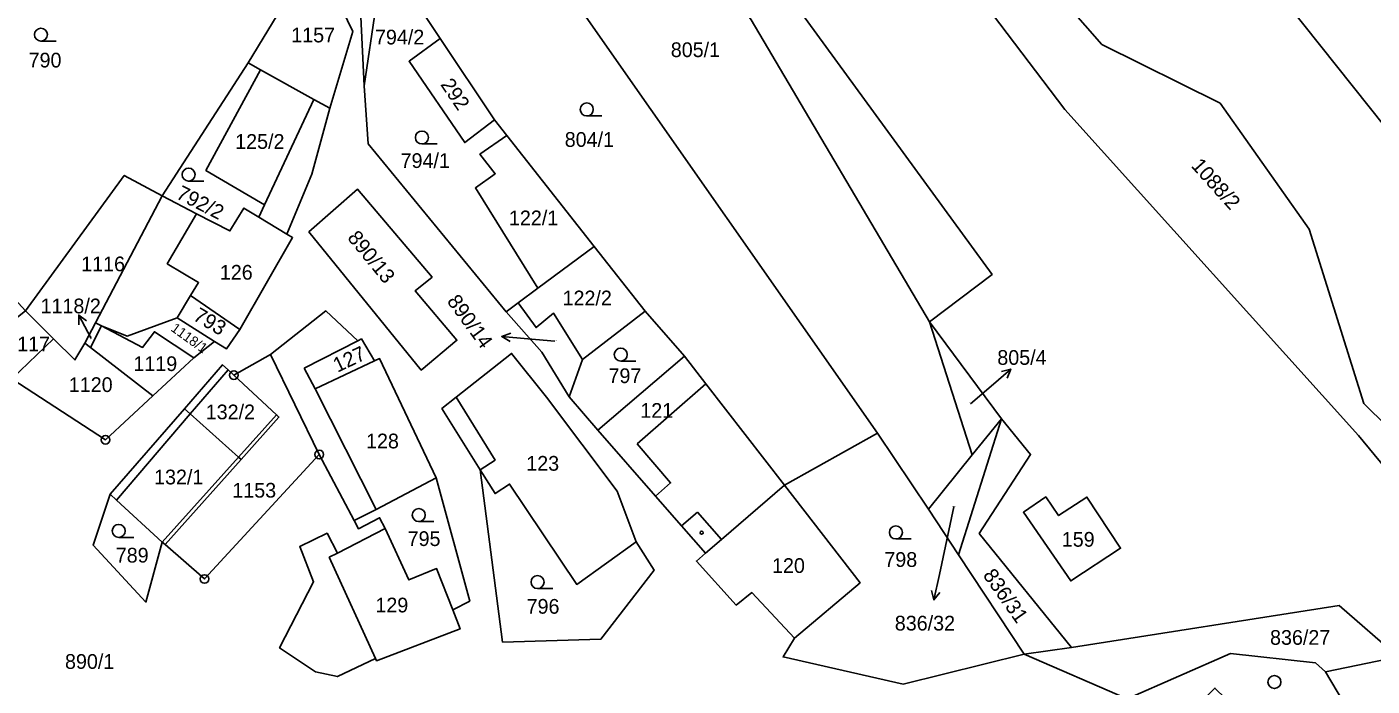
# Model space of a CAD drawing. Extents: x -654083 to -650132, y -1099819 to -1096699.
# Drawn here: x -653060.7 to -652905.4, y -1098197.5 to -1098121.3 of the extents above; entities that cross this region are included whole.
import ezdxf

# ---------------------------------------------------------------- set-up
doc = ezdxf.new("R2010")
doc.units = 0
for name, color, linetype in [('Geodetické body', 7, 'Continuous'), ('Hranice - vnitř_ kresba', 7, 'Continuous'), ('Obvody jako plochy', 7, 'Continuous'), ('Parcelní čísla', 7, 'Continuous'), ('Prvky pro prodl_ par_ č_', 7, 'Continuous'), ('Značky kultur', 7, 'Continuous'), ('Značky na budově ne v SPI', 7, 'Continuous')]:
    doc.layers.add(name, color=color, linetype=linetype)

msp = doc.modelspace()

# ---------------------------------------------------------------- linework, layer by layer
at = {"layer": 'Geodetické body'}
for centre, radius in [((-653036.79, -1098161.57), 0.5), ((-653036.79, -1098161.57), 0.001), ((-653051.6, -1098169.04), 0.5), ((-653051.6, -1098169.04), 0.001), ((-653026.93, -1098170.74), 0.5), ((-653026.93, -1098170.74), 0.001), ((-653040.19, -1098185.12), 0.5), ((-653040.19, -1098185.12), 0.001)]:
    msp.add_circle(centre, radius, dxfattribs=at)
at = {"layer": 'Hranice - vnitř_ kresba'}
for p, q in [((-653027.56, -1098129.72), (-653033.25, -1098141.9)), ((-653041.09, -1098142.92), (-653044.47, -1098148.7)), ((-653044.47, -1098148.7), (-653040.87, -1098150.87)), ((-653040.87, -1098150.87), (-653041.78, -1098152.37)), ((-653022.48, -1098157.6), (-653028.69, -1098160.78)), ((-653041.82, -1098166.06), (-653037.45, -1098160.96)), ((-653028.69, -1098160.78), (-653027.4, -1098163.17)), ((-652982.31, -1098162.56), (-652990.26, -1098169.5)), ((-653006.65, -1098171.38), (-653011.14, -1098164.13)), ((-653050.34, -1098176), (-653041.82, -1098166.06)), ((-653031.87, -1098166.14), (-653036.26, -1098171.03)), ((-652990.26, -1098169.5), (-652986.4, -1098174.03)), ((-653036.26, -1098171.03), (-653045.08, -1098180.85)), ((-653008.37, -1098172.52), (-653006.65, -1098171.38)), ((-652986.4, -1098174.03), (-652988.14, -1098175.54)), ((-652985.12, -1098178.98), (-652983.28, -1098177.39)), ((-652983.28, -1098177.39), (-652980.52, -1098180.55)), ((-653025.78, -1098182.59), (-653024.83, -1098182.13)), ((-653020.45, -1098194.29), (-653025.78, -1098182.59))]:
    msp.add_line(p, q, dxfattribs=at)
at = {"layer": 'Obvody jako plochy'}
for points in [[(-652950.77, -1098179.85), (-652944.85, -1098170.74), (-652948.2, -1098166.63), (-652956.52, -1098155.41), (-652949.3, -1098149.94), (-653000.03, -1098080.28), (-653002.88, -1098076.39), (-653023.81, -1098046.42), (-653037.15, -1098027.99), (-653053.39, -1098005.53), (-653071.26, -1097984.33), (-653150.23, -1097911.49), (-653215.43, -1097850.17), (-653263.01, -1097791.35), (-653289.74, -1097748.95), (-653316.6, -1097720.46)], [(-653147.91, -1097892.43), (-653087.66, -1097949.15), (-653051.69, -1097985.74), (-653044.45, -1097994.63), (-653022.76, -1098022.08), (-653010.09, -1098039.2), (-653001.74, -1098050.56), (-652940.91, -1098130.87), (-652906.99, -1098168.54), (-652893.23, -1098185.24), (-652886.09, -1098193.05), (-652844.83, -1098239.19), (-652818.94, -1098266.58), (-652768.04, -1098305.36), (-652748.77, -1098307.6), (-652729.64, -1098315.8), (-652661.4, -1098344.97)], [(-653062.42, -1098161.99), (-653051.6, -1098169.04), (-653046.15, -1098163.95), (-653041.4, -1098159.57), (-653039.02, -1098157.69), (-653037.66, -1098158.54), (-653036.1, -1098156.28), (-653030.01, -1098145.69), (-653030.68, -1098145.29), (-653027.79, -1098138.35), (-653025.7, -1098130.74), (-653023.08, -1098121.88), (-653027.32, -1098113)], [(-653022.15, -1098120.19), (-653021.74, -1098128.17), (-653021.28, -1098134.84), (-653005.37, -1098154.24), (-653001.25, -1098158.93), (-652998.11, -1098164.06), (-652994.8, -1098167.94), (-652988.14, -1098175.54), (-652985.12, -1098178.98), (-652982.36, -1098182.14), (-652983.42, -1098183.05), (-652978.83, -1098188.14), (-652977.01, -1098186.69), (-652972.08, -1098191.95), (-652973.42, -1098194.12), (-652959.54, -1098197.26), (-652945.6, -1098193.8), (-652933.7, -1098198.95)], [(-652631.34, -1098381.55), (-652704.64, -1098360.24), (-652738.94, -1098344.05), (-652737.17, -1098341.14), (-652773.8, -1098320.71), (-652795.83, -1098304.08), (-652826.4, -1098281.98), (-652836.28, -1098271.18), (-652854.98, -1098250.17), (-652884.09, -1098215.25), (-652902.43, -1098194.12), (-652909.24, -1098188.18), (-652940.14, -1098193.04), (-652950.77, -1098179.85)]]:
    msp.add_lwpolyline(points, dxfattribs=at)
for points in [[(-652964.91, -1098091.06), (-652936.61, -1098123.36), (-652922.98, -1098130.17), (-652912.71, -1098144.71), (-652906.4, -1098164.85), (-652887.47, -1098183.54), (-652893.23, -1098185.24), (-652906.99, -1098168.54), (-652940.91, -1098130.87), (-653001.74, -1098050.56), (-653006.39, -1098039.49), (-653002.23, -1098043.75), (-653002.01, -1098044.84), (-653000.6, -1098046.56), (-652987.25, -1098065.01), (-652985.49, -1098067.13), (-652981.58, -1098071.85), (-652973.42, -1098084.42), (-652967.92, -1098092.9)], [(-652825.33, -1098183.34), (-652882.35, -1098128.31), (-652938.91, -1098065.46), (-652934.7, -1098072.57), (-652944.94, -1098078.84), (-652930.2, -1098099.86), (-652898.24, -1098140.05), (-652895.53, -1098138.3), (-652860.37, -1098179.33), (-652847.2, -1098177.03)], [(-652860.37, -1098179.33), (-652847.2, -1098177.03), (-652825.33, -1098183.34), (-652810.18, -1098187.08), (-652821.22, -1098189.78), (-652834.98, -1098189.5), (-652863.77, -1098185.22), (-652887.47, -1098183.54), (-652906.4, -1098164.85), (-652912.71, -1098144.71), (-652922.98, -1098130.17), (-652936.61, -1098123.36), (-652964.91, -1098091.06), (-652955.6, -1098085.37), (-652944.94, -1098078.84), (-652930.2, -1098099.86), (-652898.24, -1098140.05), (-652895.53, -1098138.3)], [(-653000.03, -1098080.28), (-652949.3, -1098149.94), (-652956.52, -1098155.41), (-652977.11, -1098120.51), (-652997.92, -1098090.84), (-653000.67, -1098088.48), (-653003.49, -1098086.07)], [(-652956.65, -1098177.05), (-652962.52, -1098168.29), (-652997.48, -1098118.28), (-653011.5, -1098101.65), (-653002.18, -1098090.99), (-652997.92, -1098090.84), (-652977.11, -1098120.51), (-652956.52, -1098155.41), (-652951.59, -1098170.76)], [(-653053.71, -1098110.99), (-653055.61, -1098113.11), (-653074.21, -1098095.28), (-653077.11, -1098098), (-653091.4, -1098111.38), (-653093.32, -1098113.17), (-653082.85, -1098128.85), (-653078.13, -1098135.23), (-653060.83, -1098154.16), (-653049.44, -1098138.5), (-653045.05, -1098140.86), (-653035.15, -1098125.51), (-653030.07, -1098117.11), (-653027.32, -1098113), (-653031.29, -1098104.31), (-653037.53, -1098097.49), (-653052.73, -1098111.83)], [(-652984.78, -1098159.38), (-652989.31, -1098154.19), (-652995.2, -1098146.7), (-653005.28, -1098133.9), (-653006.71, -1098132.09), (-653012.97, -1098122.69), (-653019.03, -1098113.59), (-653011.5, -1098101.65), (-652997.48, -1098118.28), (-652962.52, -1098168.29), (-652973.23, -1098174.28), (-652982.31, -1098162.56)], [(-653027.56, -1098129.72), (-653025.7, -1098130.74), (-653023.08, -1098121.88), (-653027.32, -1098113), (-653030.07, -1098117.11), (-653035.15, -1098125.51), (-653033.73, -1098126.3)], [(-653019.82, -1098112.88), (-653019.03, -1098113.59), (-653020.41, -1098119.07), (-653021.74, -1098128.17), (-653022.15, -1098120.19)], [(-653008.39, -1098136.05), (-653006.63, -1098138.31), (-653008.92, -1098139.94), (-653001.7, -1098151.52), (-653003.97, -1098153.21), (-653005.37, -1098154.24), (-653021.28, -1098134.84), (-653021.74, -1098128.17), (-653020.41, -1098119.07), (-653019.03, -1098113.59), (-653012.97, -1098122.69), (-653016.58, -1098125.32), (-653010.15, -1098134.7), (-653006.71, -1098132.09), (-653005.28, -1098133.9)], [(-653006.71, -1098132.09), (-653012.97, -1098122.69), (-653016.58, -1098125.32), (-653010.15, -1098134.7)], [(-653012.97, -1098122.69), (-653016.58, -1098125.32), (-653010.15, -1098134.7), (-653006.71, -1098132.09)], [(-653033.25, -1098141.9), (-653040.01, -1098137.93), (-653033.73, -1098126.3), (-653035.15, -1098125.51), (-653045.05, -1098140.86), (-653041.09, -1098142.92), (-653037.25, -1098144.91), (-653035.64, -1098142.27), (-653033.92, -1098143.34)], [(-653027.56, -1098129.72), (-653033.73, -1098126.3), (-653040.01, -1098137.93), (-653033.25, -1098141.9), (-653033.92, -1098143.34), (-653030.68, -1098145.29), (-653027.79, -1098138.35), (-653025.7, -1098130.74)], [(-653027.56, -1098129.72), (-653033.25, -1098141.9), (-653040.01, -1098137.93), (-653033.73, -1098126.3)], [(-653001.7, -1098151.52), (-652995.2, -1098146.7), (-653005.28, -1098133.9), (-653008.39, -1098136.05), (-653006.63, -1098138.31), (-653008.92, -1098139.94)], [(-653005.28, -1098133.9), (-653008.39, -1098136.05), (-653006.63, -1098138.31), (-653008.92, -1098139.94), (-653001.7, -1098151.52), (-652995.2, -1098146.7)], [(-653053.99, -1098157.86), (-653052.76, -1098155.51), (-653045.05, -1098140.86), (-653049.44, -1098138.5), (-653060.83, -1098154.16), (-653057.61, -1098157.36), (-653055.14, -1098159.81)], [(-653015.86, -1098151.82), (-653013.92, -1098150.25), (-653022.51, -1098140.09), (-653028.14, -1098145.02), (-653015.17, -1098160.98), (-653011.05, -1098157.55)], [(-653011.05, -1098157.55), (-653015.86, -1098151.82), (-653013.92, -1098150.25), (-653022.51, -1098140.09), (-653028.14, -1098145.02), (-653015.17, -1098160.98)], [(-653033.92, -1098143.34), (-653030.68, -1098145.29), (-653030.01, -1098145.69), (-653036.1, -1098156.28), (-653041.78, -1098152.37), (-653043.35, -1098154.95), (-653049.1, -1098157.08), (-653052.08, -1098155.86), (-653052.76, -1098155.51), (-653045.05, -1098140.86), (-653041.09, -1098142.92), (-653037.25, -1098144.91), (-653035.64, -1098142.27)], [(-653041.09, -1098142.92), (-653044.47, -1098148.7), (-653040.87, -1098150.87), (-653041.78, -1098152.37), (-653036.1, -1098156.28), (-653030.01, -1098145.69), (-653030.68, -1098145.29), (-653033.92, -1098143.34), (-653035.64, -1098142.27), (-653037.25, -1098144.91)], [(-652995.2, -1098146.7), (-652989.31, -1098154.19), (-652996.57, -1098159.75), (-652999.89, -1098154.43), (-653001.92, -1098156.08), (-653003.97, -1098153.21), (-653001.7, -1098151.52)], [(-653003.97, -1098153.21), (-653001.7, -1098151.52), (-652995.2, -1098146.7), (-652989.31, -1098154.19), (-652996.57, -1098159.75), (-652999.89, -1098154.43), (-653001.92, -1098156.08)], [(-653041.78, -1098152.37), (-653043.35, -1098154.95), (-653039.02, -1098157.69), (-653037.66, -1098158.54), (-653036.1, -1098156.28)], [(-652996.57, -1098159.75), (-652998.11, -1098164.06), (-653001.25, -1098158.93), (-653005.37, -1098154.24), (-653003.97, -1098153.21), (-653001.92, -1098156.08), (-652999.89, -1098154.43)], [(-653062.42, -1098161.99), (-653066.55, -1098158.69), (-653060.83, -1098154.16), (-653057.61, -1098157.36)], [(-653053.32, -1098158.38), (-653052.08, -1098155.86), (-653052.76, -1098155.51), (-653053.99, -1098157.86)], [(-653045.08, -1098180.85), (-653044.73, -1098181.12), (-653040.19, -1098185.12), (-653026.93, -1098170.74), (-653022.92, -1098178.35), (-653022.41, -1098179.32), (-653019.98, -1098178.04), (-653019.32, -1098179.29), (-653024.83, -1098182.13), (-653026.03, -1098179.83), (-653029.18, -1098181.38), (-653027.6, -1098185.43), (-653031.51, -1098193.08), (-653027.37, -1098195.85), (-653024.85, -1098196.4), (-653020.45, -1098194.29), (-653020.32, -1098194.57), (-653010.68, -1098190.88), (-653011.54, -1098188.67), (-653009.58, -1098187.67), (-653013.46, -1098173.45), (-653019.98, -1098159.66), (-653020.56, -1098159.93), (-653022.08, -1098157.39), (-653022.48, -1098157.6), (-653026.19, -1098154.16), (-653032.56, -1098159.17), (-653036.79, -1098161.57), (-653037.45, -1098160.96), (-653038.09, -1098160.38), (-653042.5, -1098165.46), (-653051.07, -1098175.33), (-653053.03, -1098181.23), (-653046.94, -1098187.78)], [(-653043.35, -1098154.95), (-653039.02, -1098157.69), (-653041.4, -1098159.57), (-653045.96, -1098156.56), (-653047.32, -1098158.36), (-653052.08, -1098155.86), (-653049.1, -1098157.08)], [(-653020.36, -1098177.08), (-653022.92, -1098178.35), (-653026.93, -1098170.74), (-653032.56, -1098159.17), (-653026.19, -1098154.16), (-653022.48, -1098157.6), (-653022.08, -1098157.39), (-653020.56, -1098159.93), (-653027.4, -1098163.17)], [(-652984.78, -1098159.38), (-652994.8, -1098167.94), (-652998.11, -1098164.06), (-652996.57, -1098159.75), (-652989.31, -1098154.19)], [(-652956.52, -1098155.41), (-652948.2, -1098166.63), (-652951.59, -1098170.76)], [(-653041.4, -1098159.57), (-653045.96, -1098156.56), (-653047.32, -1098158.36), (-653052.08, -1098155.86), (-653053.32, -1098158.38), (-653046.15, -1098163.95)], [(-653055.14, -1098159.81), (-653057.61, -1098157.36), (-653062.42, -1098161.99), (-653051.6, -1098169.04), (-653046.15, -1098163.95), (-653053.32, -1098158.38), (-653053.99, -1098157.86)], [(-653028.69, -1098160.78), (-653027.4, -1098163.17), (-653020.56, -1098159.93), (-653022.08, -1098157.39), (-653022.48, -1098157.6)], [(-653026.93, -1098170.74), (-653032.56, -1098159.17), (-653036.79, -1098161.57), (-653031.87, -1098166.14), (-653031.6, -1098166.41), (-653035.96, -1098171.3), (-653044.73, -1098181.12), (-653040.19, -1098185.12)], [(-653020.36, -1098177.08), (-653013.46, -1098173.45), (-653019.98, -1098159.66), (-653020.56, -1098159.93), (-653027.4, -1098163.17)], [(-653027.4, -1098163.17), (-653020.56, -1098159.93), (-653019.98, -1098159.66), (-653013.46, -1098173.45), (-653020.36, -1098177.08)], [(-653006.64, -1098175.26), (-653004.97, -1098174.15), (-652997.22, -1098185.75), (-652990.38, -1098180.83), (-652992.54, -1098174.99), (-653000.71, -1098164.13), (-653004.74, -1098159.06), (-653011.14, -1098164.13), (-653012.79, -1098165.43), (-653008.37, -1098172.52)], [(-653011.14, -1098164.13), (-653012.79, -1098165.43), (-653008.37, -1098172.52), (-653005.78, -1098192.41), (-652994.44, -1098192.07), (-652988.3, -1098184.11), (-652990.38, -1098180.83), (-652992.54, -1098174.99), (-653000.71, -1098164.13), (-653004.74, -1098159.06)], [(-653008.37, -1098172.52), (-653006.65, -1098171.38), (-653011.14, -1098164.13), (-653004.74, -1098159.06), (-653000.71, -1098164.13), (-652992.54, -1098174.99), (-652990.38, -1098180.83), (-652997.22, -1098185.75), (-653004.97, -1098174.15), (-653006.64, -1098175.26)], [(-652980.52, -1098180.55), (-652982.36, -1098182.14), (-652985.12, -1098178.98), (-652988.14, -1098175.54), (-652994.8, -1098167.94), (-652984.78, -1098159.38), (-652982.31, -1098162.56), (-652973.23, -1098174.28)], [(-652990.26, -1098169.5), (-652986.4, -1098174.03), (-652988.14, -1098175.54), (-652994.8, -1098167.94), (-652984.78, -1098159.38), (-652982.31, -1098162.56)], [(-653036.79, -1098161.57), (-653031.87, -1098166.14), (-653031.6, -1098166.41), (-653035.96, -1098171.3), (-653036.26, -1098171.03), (-653041.82, -1098166.06), (-653042.5, -1098165.46), (-653038.09, -1098160.38), (-653037.45, -1098160.96)], [(-653037.45, -1098160.96), (-653036.79, -1098161.57), (-653031.87, -1098166.14), (-653036.26, -1098171.03), (-653041.82, -1098166.06)], [(-653041.82, -1098166.06), (-653036.26, -1098171.03), (-653035.96, -1098171.3), (-653044.73, -1098181.12), (-653045.08, -1098180.85), (-653050.34, -1098176), (-653051.07, -1098175.33), (-653042.5, -1098165.46)], [(-653045.08, -1098180.85), (-653050.34, -1098176), (-653041.82, -1098166.06), (-653036.26, -1098171.03)], [(-652948.2, -1098166.63), (-652951.59, -1098170.76), (-652956.65, -1098177.05), (-652953.16, -1098182.34)], [(-652950.77, -1098179.85), (-652940.14, -1098193.04), (-652945.6, -1098193.8), (-652953.16, -1098182.34), (-652948.2, -1098166.63), (-652944.85, -1098170.74)], [(-652956.65, -1098177.05), (-652953.16, -1098182.34), (-652945.6, -1098193.8), (-652959.54, -1098197.26), (-652973.42, -1098194.12), (-652972.08, -1098191.95), (-652964.53, -1098185.56), (-652973.23, -1098174.28), (-652962.52, -1098168.29)], [(-653008.37, -1098172.52), (-653006.64, -1098175.26), (-653004.97, -1098174.15), (-652997.22, -1098185.75), (-652990.38, -1098180.83), (-652988.3, -1098184.11), (-652994.44, -1098192.07), (-653005.78, -1098192.41)], [(-653019.32, -1098179.29), (-653016.59, -1098185.23), (-653013.39, -1098183.91), (-653011.54, -1098188.67), (-653009.58, -1098187.67), (-653013.46, -1098173.45), (-653020.36, -1098177.08), (-653022.92, -1098178.35), (-653022.41, -1098179.32), (-653019.98, -1098178.04)], [(-652964.53, -1098185.56), (-652973.23, -1098174.28), (-652980.52, -1098180.55), (-652982.36, -1098182.14), (-652983.42, -1098183.05), (-652978.83, -1098188.14), (-652977.01, -1098186.69), (-652972.08, -1098191.95)], [(-652983.42, -1098183.05), (-652978.83, -1098188.14), (-652977.01, -1098186.69), (-652972.08, -1098191.95), (-652964.53, -1098185.56), (-652973.23, -1098174.28), (-652980.52, -1098180.55), (-652982.36, -1098182.14)], [(-653050.34, -1098176), (-653051.07, -1098175.33), (-653053.03, -1098181.23), (-653046.94, -1098187.78), (-653045.08, -1098180.85)], [(-652934.47, -1098181.56), (-652938.35, -1098175.66), (-652941.61, -1098177.79), (-652943.1, -1098175.64), (-652945.68, -1098177.4), (-652940.21, -1098185.34)], [(-652943.1, -1098175.64), (-652945.68, -1098177.4), (-652940.21, -1098185.34), (-652934.47, -1098181.56), (-652938.35, -1098175.66), (-652941.61, -1098177.79)], [(-652938.35, -1098175.66), (-652941.61, -1098177.79), (-652943.1, -1098175.64), (-652945.68, -1098177.4), (-652940.21, -1098185.34), (-652934.47, -1098181.56)], [(-653013.39, -1098183.91), (-653011.54, -1098188.67), (-653010.68, -1098190.88), (-653020.32, -1098194.57), (-653020.45, -1098194.29), (-653024.85, -1098196.4), (-653027.37, -1098195.85), (-653031.51, -1098193.08), (-653027.6, -1098185.43), (-653029.18, -1098181.38), (-653026.03, -1098179.83), (-653024.83, -1098182.13), (-653019.32, -1098179.29), (-653016.59, -1098185.23)], [(-653025.78, -1098182.59), (-653024.83, -1098182.13), (-653019.32, -1098179.29), (-653016.59, -1098185.23), (-653013.39, -1098183.91), (-653011.54, -1098188.67), (-653010.68, -1098190.88), (-653020.32, -1098194.57), (-653020.45, -1098194.29)], [(-652902.43, -1098194.12), (-652910.83, -1098195.85), (-652911.98, -1098194.81), (-652921.78, -1098193.71), (-652933.7, -1098198.95), (-652945.6, -1098193.8), (-652940.14, -1098193.04), (-652909.24, -1098188.18)], [(-652908.74, -1098199.34), (-652910.83, -1098195.85), (-652911.98, -1098194.81), (-652921.78, -1098193.71), (-652933.7, -1098198.95), (-652937.16, -1098206.65), (-652933.63, -1098209.39), (-652930.14, -1098207.39), (-652931.64, -1098205.84), (-652923.57, -1098197.73), (-652919.83, -1098201.39), (-652915.4, -1098205.73)], [(-652894.01, -1098232.83), (-652897.12, -1098229.88), (-652900.37, -1098234.02), (-652912.62, -1098224.07), (-652900.33, -1098210.94), (-652908.74, -1098199.34), (-652910.83, -1098195.85), (-652902.43, -1098194.12), (-652884.09, -1098215.25), (-652890.34, -1098222.72), (-652882.1, -1098230.56), (-652888.87, -1098237.69), (-652892.06, -1098234.68), (-652893.16, -1098235.84), (-652895.11, -1098233.99)]]:
    msp.add_lwpolyline(points, close=True, dxfattribs=at)
at = {"layer": 'Prvky pro prodl_ par_ č_'}
for p, q in [((-653053.29, -1098157.28), (-653054.7, -1098154.63)), ((-653002.88, -1098157.37), (-653005.87, -1098157.12)), ((-653053.26, -1098157.33), (-653053.29, -1098157.28)), ((-652999.76, -1098157.63), (-653002.88, -1098157.37)), ((-652949.41, -1098162.83), (-652947.13, -1098160.88)), ((-652951.8, -1098164.87), (-652949.41, -1098162.83)), ((-652953.69, -1098176.77), (-652955.38, -1098184.61)), ((-652955.38, -1098184.61), (-652956.01, -1098187.54))]:
    msp.add_line(p, q, dxfattribs=at)
for points in [[(-653054.67, -1098155.75), (-653054.7, -1098154.63), (-653053.79, -1098155.28)], [(-653004.91, -1098157.7), (-653005.87, -1098157.12), (-653004.83, -1098156.71)], [(-652948.22, -1098161.15), (-652947.13, -1098160.88), (-652947.57, -1098161.91)], [(-652955.31, -1098186.67), (-652956.01, -1098187.54), (-652956.29, -1098186.46)]]:
    msp.add_lwpolyline(points, dxfattribs=at)
at = {"layer": 'Značky kultur'}
for p, q in [((-653057.3, -1098122.99), (-653059.05, -1098122.99)), ((-652994.31, -1098131.63), (-652996.06, -1098131.63)), ((-653013.34, -1098134.87), (-653015.09, -1098134.87)), ((-653040.26, -1098139.16), (-653042.01, -1098139.16)), ((-652990.39, -1098159.95), (-652992.14, -1098159.95)), ((-653013.7, -1098178.48), (-653015.45, -1098178.48)), ((-653048.33, -1098180.31), (-653050.08, -1098180.31)), ((-652958.65, -1098180.49), (-652960.4, -1098180.49)), ((-653000, -1098186.22), (-653001.75, -1098186.22))]:
    msp.add_line(p, q, dxfattribs=at)
for centre in [(-653059.05, -1098122.24), (-652996.06, -1098130.88), (-653015.09, -1098134.12), (-653042.01, -1098138.41), (-652992.14, -1098159.2), (-653015.45, -1098177.73), (-653050.08, -1098179.56), (-652960.4, -1098179.74), (-653001.75, -1098185.47), (-652916.71, -1098197.02)]:
    msp.add_circle(centre, 0.75, dxfattribs=at)
at = {"layer": 'Značky na budově ne v SPI'}
msp.add_circle((-652982.81, -1098179.77), 0.175, dxfattribs=at)

# ---------------------------------------------------------------- texts
at = {"layer": 'Parcelní čísla'}
for s, height, p in [('1157', 1.7, (-653030.17, -1098123.13)), ('805/1', 1.7, (-652986.37, -1098124.83)), ('790', 1.7, (-653060.48, -1098126.03)), ('125/2', 1.7, (-653036.64, -1098135.43)), ('804/1', 1.7, (-652998.61, -1098135.2)), ('794/1', 1.7, (-653017.55, -1098137.64)), ('122/1', 1.7, (-653005.05, -1098144.26)), ('1116', 1.7, (-653054.41, -1098149.57)), ('126', 1.7, (-653038.41, -1098150.54)), ('122/2', 1.7, (-652998.86, -1098153.51)), ('1117', 1.7, (-653063.06, -1098158.82)), ('890/14', 0.1, (-652999.96, -1098157.63)), ('1119', 1.7, (-653048.39, -1098161.1)), ('1120', 1.7, (-653055.84, -1098163.52)), ('797', 1.7, (-652993.56, -1098162.49)), ('132/2', 1.7, (-653040.04, -1098166.67)), ('121', 1.7, (-652989.89, -1098166.5)), ('805/4', 0.1, (-652951.98, -1098164.87)), ('128', 1.7, (-653021.54, -1098170.03)), ('123', 1.7, (-653003.05, -1098172.61)), ('132/1', 1.7, (-653046, -1098174.19)), ('1153', 1.7, (-653036.97, -1098175.72)), ('836/32', 0.1, (-652953.92, -1098176.77)), ('795', 1.7, (-653016.74, -1098181.31)), ('159', 1.7, (-652941.25, -1098181.39)), ('789', 1.7, (-653050.42, -1098183.22)), ('798', 1.7, (-652961.73, -1098183.72)), ('120', 1.7, (-652974.69, -1098184.42)), ('129', 1.7, (-653020.46, -1098188.98)), ('796', 1.7, (-653003.01, -1098189.13)), ('836/27', 1.7, (-652917.22, -1098192.72)), ('890/1', 1.7, (-653056.28, -1098195.5))]:
    msp.add_text(s, height=height, dxfattribs=at).set_placement(p)
for s, height, rotation, p in [('292', 1.7, 304.074, (-653013.01, -1098128)), ('1088/2', 1.7, 311.895, (-652926.41, -1098137.44)), ('792/2', 1.7, 332.946, (-653043.57, -1098141.09)), ('890/13', 1.7, 309.141, (-653023.77, -1098145.74)), ('793', 1.7, 329.337, (-653041.61, -1098155.13)), ('1118/2', 0.1, 64.683, (-653053.33, -1098157.48)), ('1118/1', 1.14, 324.324, (-653044.15, -1098156.38)), ('127', 1.7, 25.2, (-653024.84, -1098161.3)), ('836/31', 1.7, 305.172, (-652950.42, -1098184.69))]:
    msp.add_text(s, height=height, rotation=rotation, dxfattribs=at).set_placement(p)
at = {"layer": 'Prvky pro prodl_ par_ č_'}
for s, p in [('794/2', (-653020.51, -1098123.37)), ('1118/2', (-653059.1, -1098154.43)), ('805/4', (-652948.69, -1098160.38)), ('836/32', (-652960.52, -1098191.07))]:
    msp.add_text(s, height=1.7, dxfattribs=at).set_placement(p)
msp.add_text('890/14', height=1.7, rotation=306.072, dxfattribs=at).set_placement((-653012.27, -1098153.04))

doc.saveas('drawing.dxf')
